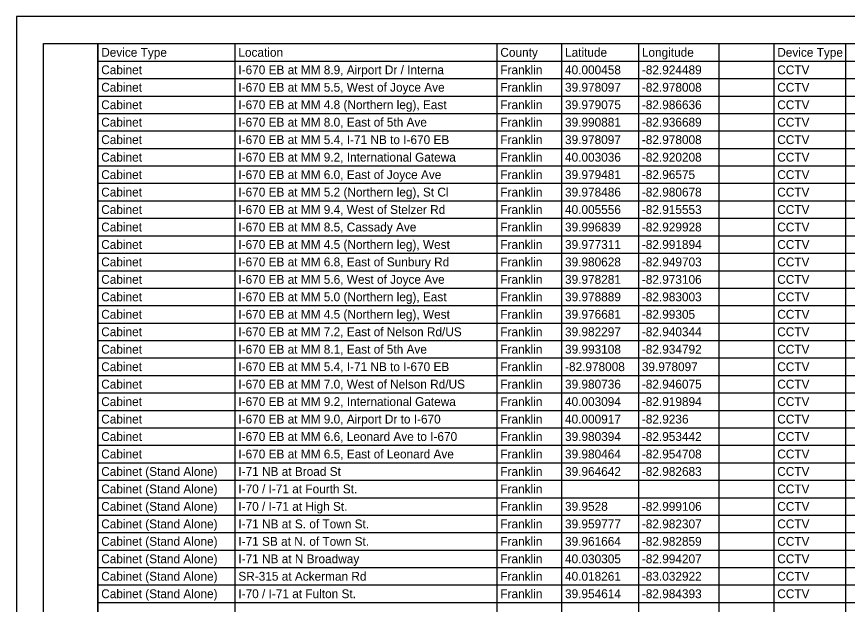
# Model space of a CAD drawing. Extents: x 0 to 34, y 0 to 22.
# Drawn here: x 0 to 15.36, y 11.13 to 22 of the extents above; entities that cross this region are included whole.
import ezdxf

# ---------------------------------------------------------------- set-up
doc = ezdxf.new("R2010")
doc.units = 0
for name, color, linetype in [('SH_Border', 7, 'Continuous'), ('SH_Cut_Line', 7, 'Continuous'), ('SH_Text', 7, 'Continuous')]:
    doc.layers.add(name, color=color, linetype=linetype)

msp = doc.modelspace()

# ---------------------------------------------------------------- linework, layer by layer
at = {"layer": 'SH_Border'}
for points in [[(0.5, 21.5), (1.5, 21.5), (1.5, 0.5), (0.5, 0.5)], [(1.5, 21.5), (33.5, 21.5), (33.5, 0.5), (1.5, 0.5)]]:
    msp.add_lwpolyline(points, close=True, dxfattribs=at)
at = {"layer": 'SH_Cut_Line'}
msp.add_lwpolyline([(0, 0), (34, 0), (34, 22), (0, 22)], close=True, dxfattribs=at)
at = {"layer": 'SH_Text'}
for p, q in [((1.5, 21.5), (26.278, 21.5)), ((1.5, 21.5), (1.5, 0.502)), ((4.036, 21.5), (4.036, 0.502)), ((8.882, 21.5), (8.882, 0.502)), ((10.077, 21.5), (10.077, 0.502)), ((11.498, 21.5), (11.498, 0.502)), ((12.984, 21.5), (12.984, 0.502)), ((14.002, 21.5), (14.002, 0.502)), ((15.326, 21.5), (15.326, 0.502)), ((1.5, 21.177), (26.278, 21.177)), ((1.5, 20.854), (26.278, 20.854)), ((1.5, 20.531), (26.278, 20.531)), ((1.5, 20.208), (26.278, 20.208)), ((1.5, 19.885), (26.278, 19.885)), ((1.5, 19.562), (26.278, 19.562)), ((1.5, 19.239), (26.278, 19.239)), ((1.5, 18.916), (26.278, 18.916)), ((1.5, 18.593), (26.278, 18.593)), ((1.5, 18.27), (26.278, 18.27)), ((1.5, 17.946), (26.278, 17.946)), ((1.5, 17.623), (26.278, 17.623)), ((1.5, 17.3), (26.278, 17.3)), ((1.5, 16.977), (26.278, 16.977)), ((1.5, 16.654), (26.278, 16.654)), ((1.5, 16.331), (26.278, 16.331)), ((1.5, 16.008), (26.278, 16.008)), ((1.5, 15.685), (26.278, 15.685)), ((1.5, 15.362), (26.278, 15.362)), ((1.5, 15.039), (26.278, 15.039)), ((1.5, 14.716), (26.278, 14.716)), ((1.5, 14.393), (26.278, 14.393)), ((1.5, 14.07), (26.278, 14.07)), ((1.5, 13.747), (26.278, 13.747)), ((1.5, 13.424), (26.278, 13.424)), ((1.5, 13.101), (26.278, 13.101)), ((1.5, 12.778), (26.278, 12.778)), ((1.5, 12.455), (26.278, 12.455)), ((1.5, 12.132), (26.278, 12.132)), ((1.5, 11.809), (26.278, 11.809)), ((1.5, 11.486), (26.278, 11.486)), ((1.5, 11.162), (26.278, 11.162))]:
    msp.add_line(p, q, dxfattribs=at)

# ---------------------------------------------------------------- texts
for s, height, p in [('Device Type', 0.16346, (1.565, 21.257)), ('Location', 0.1635, (4.101, 21.257)), ('County', 0.1635, (8.946, 21.257)), ('Latitude', 0.1635, (10.142, 21.257)), ('Longitude', 0.1635, (11.563, 21.257)), ('Device Type', 0.16346, (14.067, 21.257)), ('Cabinet', 0.1635, (1.565, 20.934)), ('I-670 EB at MM 8.9, Airport Dr / Interna', 0.16346, (4.101, 20.934)), ('Franklin', 0.1635, (8.946, 20.934)), ('40.000458', 0.1635, (10.142, 20.934)), ('-82.924489', 0.1635, (11.563, 20.934)), ('CCTV', 0.1635, (14.067, 20.934)), ('Cabinet', 0.1635, (1.565, 20.611)), ('I-670 EB at MM 5.5, West of Joyce Ave', 0.16346, (4.101, 20.611)), ('Franklin', 0.1635, (8.946, 20.611)), ('39.978097', 0.1635, (10.142, 20.611)), ('-82.978008', 0.1635, (11.563, 20.611)), ('CCTV', 0.1635, (14.067, 20.611)), ('Cabinet', 0.1635, (1.565, 20.288)), ('I-670 EB at MM 4.8 (Northern leg), East', 0.16346, (4.101, 20.288)), ('Franklin', 0.1635, (8.946, 20.288)), ('39.979075', 0.1635, (10.142, 20.288)), ('-82.986636', 0.1635, (11.563, 20.288)), ('CCTV', 0.1635, (14.067, 20.288)), ('Cabinet', 0.1635, (1.565, 19.965)), ('I-670 EB at MM 8.0, East of 5th Ave', 0.16346, (4.101, 19.965)), ('Franklin', 0.1635, (8.946, 19.965)), ('39.990881', 0.1635, (10.142, 19.965)), ('-82.936689', 0.1635, (11.563, 19.965)), ('CCTV', 0.1635, (14.067, 19.965)), ('Cabinet', 0.1635, (1.565, 19.642)), ('I-670 EB at MM 5.4, I-71 NB to I-670 EB', 0.16346, (4.101, 19.642)), ('Franklin', 0.1635, (8.946, 19.642)), ('39.978097', 0.1635, (10.142, 19.642)), ('-82.978008', 0.1635, (11.563, 19.642)), ('CCTV', 0.1635, (14.067, 19.642)), ('Cabinet', 0.1635, (1.565, 19.318)), ('I-670 EB at MM 9.2, International Gatewa', 0.16346, (4.101, 19.318)), ('Franklin', 0.1635, (8.946, 19.318)), ('40.003036', 0.1635, (10.142, 19.318)), ('-82.920208', 0.1635, (11.563, 19.318)), ('CCTV', 0.1635, (14.067, 19.318)), ('Cabinet', 0.1635, (1.565, 18.995)), ('I-670 EB at MM 6.0, East of Joyce Ave', 0.16346, (4.101, 18.995)), ('Franklin', 0.1635, (8.946, 18.995)), ('39.979481', 0.1635, (10.142, 18.995)), ('-82.96575', 0.1635, (11.563, 18.995)), ('CCTV', 0.1635, (14.067, 18.995)), ('Cabinet', 0.1635, (1.565, 18.672)), ('I-670 EB at MM 5.2 (Northern leg), St Cl', 0.16346, (4.101, 18.672)), ('Franklin', 0.1635, (8.946, 18.672)), ('39.978486', 0.1635, (10.142, 18.672)), ('-82.980678', 0.1635, (11.563, 18.672)), ('CCTV', 0.1635, (14.067, 18.672)), ('Cabinet', 0.1635, (1.565, 18.349)), ('I-670 EB at MM 9.4, West of Stelzer Rd', 0.16346, (4.101, 18.349)), ('Franklin', 0.1635, (8.946, 18.349)), ('40.005556', 0.1635, (10.142, 18.349)), ('-82.915553', 0.1635, (11.563, 18.349)), ('CCTV', 0.1635, (14.067, 18.349)), ('Cabinet', 0.1635, (1.565, 18.026)), ('I-670 EB at MM 8.5, Cassady Ave', 0.16346, (4.101, 18.026)), ('Franklin', 0.1635, (8.946, 18.026)), ('39.996839', 0.1635, (10.142, 18.026)), ('-82.929928', 0.1635, (11.563, 18.026)), ('CCTV', 0.1635, (14.067, 18.026)), ('Cabinet', 0.1635, (1.565, 17.703)), ('I-670 EB at MM 4.5 (Northern leg), West', 0.16346, (4.101, 17.703)), ('Franklin', 0.1635, (8.946, 17.703)), ('39.977311', 0.1635, (10.142, 17.703)), ('-82.991894', 0.1635, (11.563, 17.703)), ('CCTV', 0.1635, (14.067, 17.703)), ('Cabinet', 0.1635, (1.565, 17.38)), ('I-670 EB at MM 6.8, East of Sunbury Rd', 0.16346, (4.101, 17.38)), ('Franklin', 0.1635, (8.946, 17.38)), ('39.980628', 0.1635, (10.142, 17.38)), ('-82.949703', 0.1635, (11.563, 17.38)), ('CCTV', 0.1635, (14.067, 17.38)), ('Cabinet', 0.1635, (1.565, 17.057)), ('I-670 EB at MM 5.6, West of Joyce Ave', 0.16346, (4.101, 17.057)), ('Franklin', 0.1635, (8.946, 17.057)), ('39.978281', 0.1635, (10.142, 17.057)), ('-82.973106', 0.1635, (11.563, 17.057)), ('CCTV', 0.1635, (14.067, 17.057)), ('Cabinet', 0.1635, (1.565, 16.734)), ('I-670 EB at MM 5.0 (Northern leg), East', 0.16346, (4.101, 16.734)), ('Franklin', 0.1635, (8.946, 16.734)), ('39.978889', 0.1635, (10.142, 16.734)), ('-82.983003', 0.1635, (11.563, 16.734)), ('CCTV', 0.1635, (14.067, 16.734)), ('Cabinet', 0.1635, (1.565, 16.411)), ('I-670 EB at MM 4.5 (Northern leg), West', 0.16346, (4.101, 16.411)), ('Franklin', 0.1635, (8.946, 16.411)), ('39.976681', 0.1635, (10.142, 16.411)), ('-82.99305', 0.1635, (11.563, 16.411)), ('CCTV', 0.1635, (14.067, 16.411)), ('Cabinet', 0.1635, (1.565, 16.088)), ('I-670 EB at MM 7.2, East of Nelson Rd/US', 0.16346, (4.101, 16.088)), ('Franklin', 0.1635, (8.946, 16.088)), ('39.982297', 0.1635, (10.142, 16.088)), ('-82.940344', 0.1635, (11.563, 16.088)), ('CCTV', 0.1635, (14.067, 16.088)), ('Cabinet', 0.1635, (1.565, 15.765)), ('I-670 EB at MM 8.1, East of 5th Ave', 0.16346, (4.101, 15.765)), ('Franklin', 0.1635, (8.946, 15.765)), ('39.993108', 0.1635, (10.142, 15.765)), ('-82.934792', 0.1635, (11.563, 15.765)), ('CCTV', 0.1635, (14.067, 15.765)), ('Cabinet', 0.1635, (1.565, 15.442)), ('I-670 EB at MM 5.4, I-71 NB to I-670 EB', 0.16346, (4.101, 15.442)), ('Franklin', 0.1635, (8.946, 15.442)), ('-82.978008', 0.1635, (10.142, 15.442)), ('39.978097', 0.1635, (11.563, 15.442)), ('CCTV', 0.1635, (14.067, 15.442)), ('Cabinet', 0.1635, (1.565, 15.119)), ('I-670 EB at MM 7.0, West of Nelson Rd/US', 0.16346, (4.101, 15.119)), ('Franklin', 0.1635, (8.946, 15.119)), ('39.980736', 0.1635, (10.142, 15.119)), ('-82.946075', 0.1635, (11.563, 15.119)), ('CCTV', 0.1635, (14.067, 15.119)), ('Cabinet', 0.1635, (1.565, 14.796)), ('I-670 EB at MM 9.2, International Gatewa', 0.16346, (4.101, 14.796)), ('Franklin', 0.1635, (8.946, 14.796)), ('40.003094', 0.1635, (10.142, 14.796)), ('-82.919894', 0.1635, (11.563, 14.796)), ('CCTV', 0.1635, (14.067, 14.796)), ('Cabinet', 0.1635, (1.565, 14.473)), ('I-670 EB at MM 9.0, Airport Dr to I-670', 0.16346, (4.101, 14.473)), ('Franklin', 0.1635, (8.946, 14.473)), ('40.000917', 0.1635, (10.142, 14.473)), ('-82.9236', 0.1635, (11.563, 14.473)), ('CCTV', 0.1635, (14.067, 14.473)), ('Cabinet', 0.1635, (1.565, 14.15)), ('I-670 EB at MM 6.6, Leonard Ave to I-670', 0.16346, (4.101, 14.15)), ('Franklin', 0.1635, (8.946, 14.15)), ('39.980394', 0.1635, (10.142, 14.15)), ('-82.953442', 0.1635, (11.563, 14.15)), ('CCTV', 0.1635, (14.067, 14.15)), ('Cabinet', 0.1635, (1.565, 13.827)), ('I-670 EB at MM 6.5, East of Leonard Ave', 0.16346, (4.101, 13.827)), ('Franklin', 0.1635, (8.946, 13.827)), ('39.980464', 0.1635, (10.142, 13.827)), ('-82.954708', 0.1635, (11.563, 13.827)), ('CCTV', 0.1635, (14.067, 13.827)), ('Cabinet (Stand Alone)', 0.16346, (1.565, 13.504)), ('I-71 NB at Broad St', 0.16346, (4.101, 13.504)), ('Franklin', 0.1635, (8.946, 13.504)), ('39.964642', 0.1635, (10.142, 13.504)), ('-82.982683', 0.1635, (11.563, 13.504)), ('CCTV', 0.1635, (14.067, 13.504)), ('Cabinet (Stand Alone)', 0.16346, (1.565, 13.181)), ('I-70 / I-71 at Fourth St.', 0.16346, (4.101, 13.181)), ('Franklin', 0.1635, (8.946, 13.181)), ('CCTV', 0.1635, (14.067, 13.181)), ('Cabinet (Stand Alone)', 0.16346, (1.565, 12.858)), ('I-70 / I-71 at High St.', 0.16346, (4.101, 12.858)), ('Franklin', 0.1635, (8.946, 12.858)), ('39.9528', 0.1635, (10.142, 12.858)), ('-82.999106', 0.1635, (11.563, 12.858)), ('CCTV', 0.1635, (14.067, 12.858)), ('Cabinet (Stand Alone)', 0.16346, (1.565, 12.534)), ('I-71 NB at S. of Town St.', 0.16346, (4.101, 12.534)), ('Franklin', 0.1635, (8.946, 12.534)), ('39.959777', 0.1635, (10.142, 12.534)), ('-82.982307', 0.1635, (11.563, 12.534)), ('CCTV', 0.1635, (14.067, 12.534)), ('Cabinet (Stand Alone)', 0.16346, (1.565, 12.211)), ('I-71 SB at N. of Town St.', 0.16346, (4.101, 12.211)), ('Franklin', 0.1635, (8.946, 12.211)), ('39.961664', 0.1635, (10.142, 12.211)), ('-82.982859', 0.1635, (11.563, 12.211)), ('CCTV', 0.1635, (14.067, 12.211)), ('Cabinet (Stand Alone)', 0.16346, (1.565, 11.888)), ('I-71 NB at N Broadway', 0.16346, (4.101, 11.888)), ('Franklin', 0.1635, (8.946, 11.888)), ('40.030305', 0.1635, (10.142, 11.888)), ('-82.994207', 0.1635, (11.563, 11.888)), ('CCTV', 0.1635, (14.067, 11.888)), ('Cabinet (Stand Alone)', 0.16346, (1.565, 11.565)), ('SR-315 at Ackerman Rd', 0.16346, (4.101, 11.565)), ('Franklin', 0.1635, (8.946, 11.565)), ('40.018261', 0.1635, (10.142, 11.565)), ('-83.032922', 0.1635, (11.563, 11.565)), ('CCTV', 0.1635, (14.067, 11.565)), ('Cabinet (Stand Alone)', 0.16346, (1.565, 11.242)), ('I-70 / I-71 at Fulton St.', 0.16346, (4.101, 11.242)), ('Franklin', 0.1635, (8.946, 11.242)), ('39.954614', 0.1635, (10.142, 11.242)), ('-82.984393', 0.1635, (11.563, 11.242)), ('CCTV', 0.1635, (14.067, 11.242))]:
    msp.add_text(s, height=height, dxfattribs=at).set_placement(p)

doc.saveas('drawing.dxf')
